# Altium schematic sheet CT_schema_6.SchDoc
size 278 x 170 mm
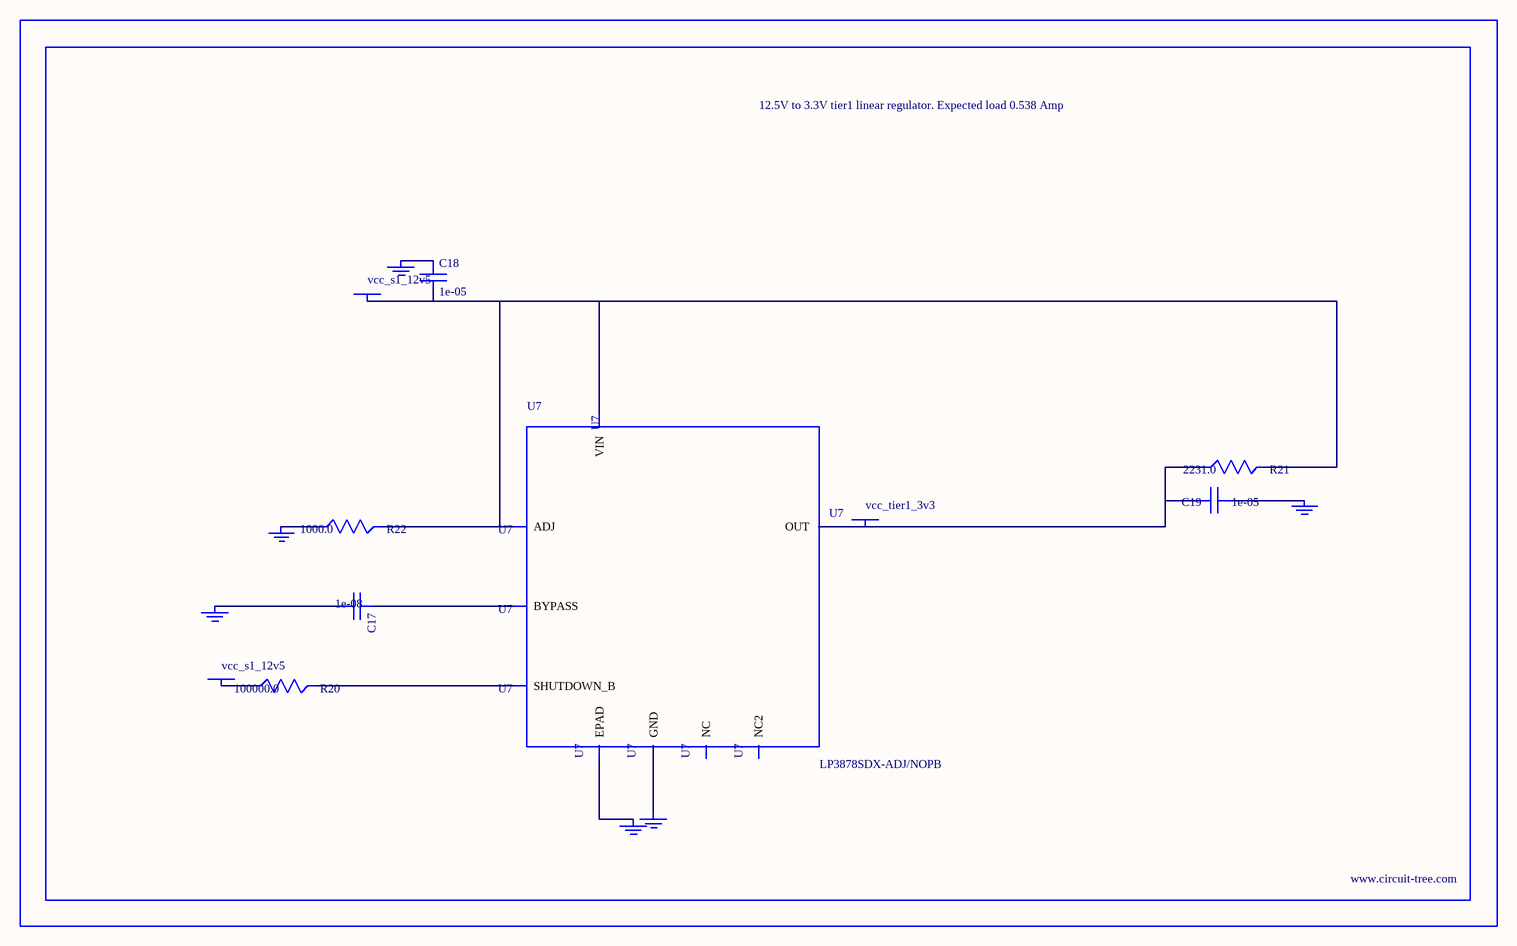
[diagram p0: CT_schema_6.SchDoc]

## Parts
BORDER5  (no value)
C17  1e-08  [C0402]
C18  1e-05  [C1210]
C19  1e-05  [C1210]
GND_INSTANCE_5_0  (no value)
GND_INSTANCE_5_1  (no value)
GND_INSTANCE_5_2  (no value)
GND_INSTANCE_5_3  (no value)
GND_INSTANCE_5_4  (no value)
GND_INSTANCE_5_5  (no value)
POWER_INSTANCE_5_0  vcc_s1_12v5
POWER_INSTANCE_5_1  vcc_s1_12v5
POWER_INSTANCE_5_2  vcc_tier1_3v3
R20  100000.0  [R0603]
R21  2231.0  [R0603]
R22  1000.0  [R0603]
U7  LP3878SDX-ADJ/NOPB  [WSON-8]

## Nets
NetC17_1: C17.1 U7.1(BYPASS)
NetC17_2: C17.2 GND_INSTANCE_5_0.0(GND)
NetC18_1: C18.1 GND_INSTANCE_5_1.0(GND)
NetC18_2: C18.2 POWER_INSTANCE_5_0.0(PWR) R21.2 R22.2 U7.4(VIN) U7.6(ADJ)
NetC19_1: C19.1 GND_INSTANCE_5_2.0(GND)
NetC19_2: C19.2 POWER_INSTANCE_5_2.0(PWR) R21.1 U7.5(OUT)
NetGND_INSTANCE_5_3_0: GND_INSTANCE_5_3.0(GND) R22.1
NetGND_INSTANCE_5_4_0: GND_INSTANCE_5_4.0(GND) U7.PAD(EPAD)
NetGND_INSTANCE_5_5_0: GND_INSTANCE_5_5.0(GND) U7.3(GND)
NetPOWER_INSTANCE_5_1_0: POWER_INSTANCE_5_1.0(PWR) R20.1
NetR20_2: R20.2 U7.8(SHUTDOWN_B)

Not connected (* = marked no-connect by the designer): U7 2(NC) 7(NC2)

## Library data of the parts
BORDER5 = BORDER_PAGE5
C17 = C0402C103K3RAC
C18 = C1210C106K5PACTU
C19 = GRM32DR61E106MA12L
GND_INSTANCE_5_0-GND_INSTANCE_5_5 = GND
POWER_INSTANCE_5_0-POWER_INSTANCE_5_2 = PWR
R20 = RC0603JR-07100KL
R21 = R21
R22 = RC0603JR-071KL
